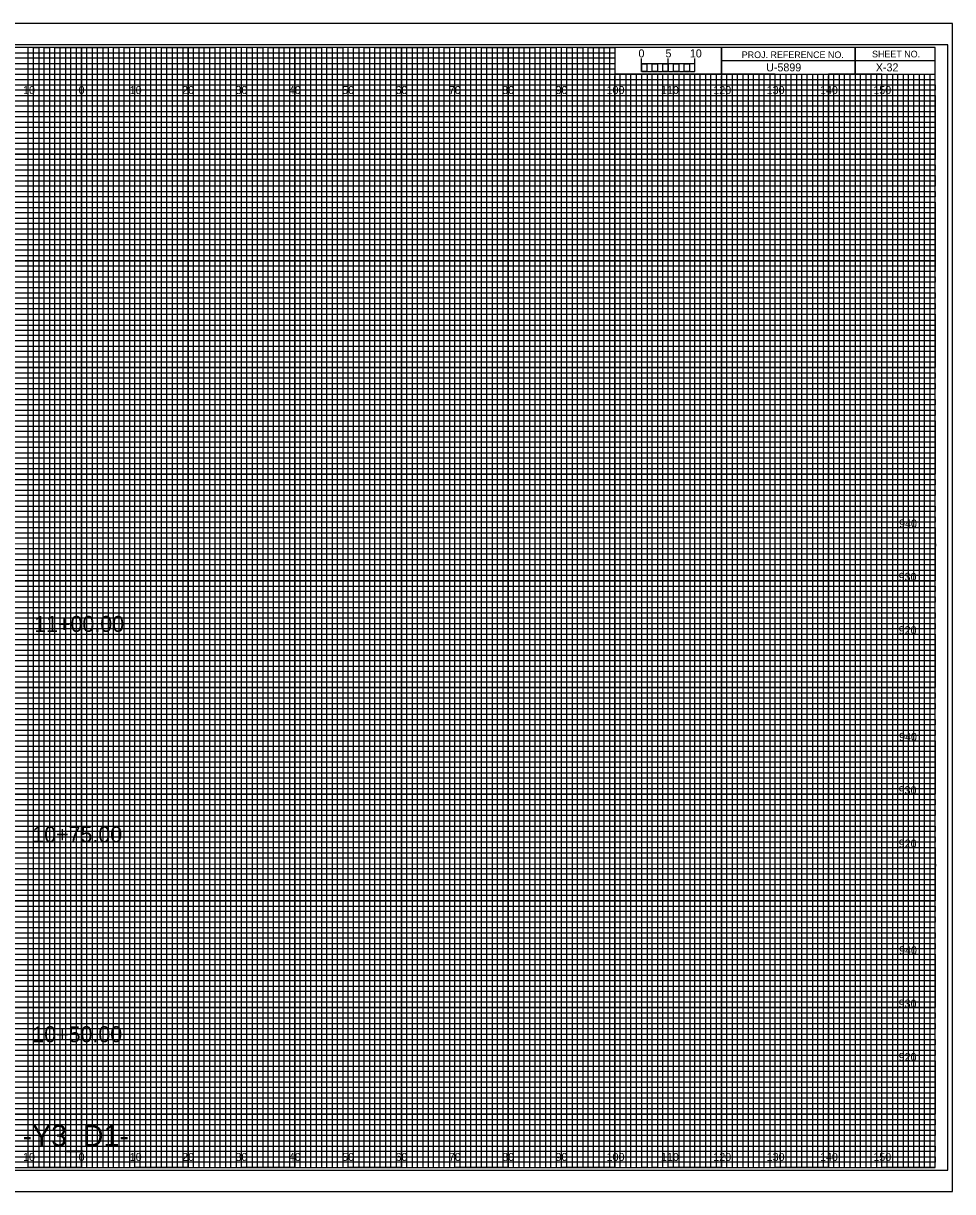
# Model space of a CAD drawing. Extents: x -13 to 323, y -4 to 214.
# Drawn here: x 149.1 to 323.3, y -4.5 to 214.5 of the extents above; entities that cross this region are included whole.
import ezdxf

# ---------------------------------------------------------------- set-up
doc = ezdxf.new("R2010")
doc.units = 0
for name, color, linetype in [('Prop XS Alignment Label', 7, 'Continuous'), ('Prop XS Bar Scale Labels', 7, 'Continuous'), ('Prop XS Elevation Labels', 7, 'Continuous'), ('Prop XS Offset Labels', 7, 'Continuous'), ('Prop XS Project Number', 7, 'Continuous'), ('Prop XS Sheet Number', 7, 'Continuous'), ('Prop XS Station Labels', 7, 'Continuous'), ('Sheet Cross Section CELL', 7, 'Continuous'), ('Sheet Cross Section Grid Major CELL', 7, 'Continuous'), ('Sheet Cross Section Grid Middle CELL', 7, 'Continuous'), ('Sheet Cross Section Grid Minor 1 CELL', 7, 'Continuous'), ('Sheet Cross Section Grid Minor 2 CELL', 7, 'Continuous'), ('Sheet Cross Section Scale CELL', 7, 'Continuous'), ('Sheet Cutting Line CELL', 7, 'Continuous'), ('Sheet DOT Grid CELL', 7, 'Continuous'), ('Sheet Plot Border Inside CELL', 7, 'Continuous'), ('Sheet Plot Border Outside CELL', 7, 'Continuous')]:
    doc.layers.add(name, color=color, linetype=linetype)

msp = doc.modelspace()

# ---------------------------------------------------------------- linework, layer by layer
at = {"layer": 'Sheet Cross Section CELL'}
for p, q in [((305, 210), (305, 205)), ((305, 205), (305, 210)), ((280, 207.5), (280, 205)), ((320, 207.49), (280, 207.49)), ((280, 205), (320, 205))]:
    msp.add_line(p, q, dxfattribs=at)
for points in [[(320, 210), (0, 210), (0, 0), (320, 0)], [(280, 210), (260, 210), (260, 205.03), (280, 205.03)], [(320, 210), (280, 210), (280, 205), (320, 205)]]:
    msp.add_lwpolyline(points, close=True, dxfattribs=at)
at = {"layer": 'Sheet Cross Section Grid Major CELL'}
for p, q in [((150, 210), (140, 210)), ((150, 0), (150, 210)), ((170, 210), (160, 210)), ((160, 210), (160, 0)), ((170, 0), (170, 210)), ((190, 210), (180, 210)), ((180, 210), (180, 0)), ((190, 0), (190, 210)), ((210, 210), (200, 210)), ((200, 210), (200, 0)), ((210, 0), (210, 210)), ((230, 210), (220, 210)), ((220, 210), (220, 0)), ((230, 0), (230, 210)), ((250, 210), (240, 210)), ((240, 210), (240, 0)), ((250, 0), (250, 210)), ((260, 210), (260, 0)), ((270, 0), (270, 205)), ((290, 205), (280, 205)), ((280, 205), (280, 0)), ((290, 0), (290, 205)), ((310, 205), (300, 205)), ((300, 205), (300, 0)), ((310, 0), (310, 205)), ((160, 0), (150, 0)), ((180, 0), (170, 0)), ((200, 0), (190, 0)), ((220, 0), (210, 0)), ((240, 0), (230, 0)), ((260, 0), (250, 0)), ((280, 0), (270, 0)), ((300, 0), (290, 0)), ((320, 0), (310, 0)), ((320, 0), (320, 0))]:
    msp.add_line(p, q, dxfattribs=at)
for points in [[(0, 200), (320, 200), (320, 190), (0, 190)], [(0, 180), (320, 180), (320, 170), (0, 170)], [(0, 160), (320, 160), (320, 150), (0, 150)], [(0, 140), (320, 140), (320, 130), (0, 130)], [(0, 120), (320, 120), (320, 110), (0, 110)], [(0, 100), (320, 100), (320, 90), (0, 90)], [(0, 80), (320, 80), (320, 70), (0, 70)], [(0, 60), (320, 60), (320, 50), (0, 50)], [(0, 40), (320, 40), (320, 30), (0, 30)], [(0, 20), (320, 20), (320, 10), (0, 10)]]:
    msp.add_lwpolyline(points, dxfattribs=at)
at = {"layer": 'Sheet Cross Section Grid Middle CELL'}
for points in [[(145, 0), (155, 0), (155, 210), (165, 210), (165, 0), (175, 0), (175, 210), (185, 210), (185, 0), (195, 0), (195, 210), (205, 210), (205, 0), (215, 0), (215, 210), (225, 210), (225, 0), (235, 0), (235, 210), (245, 210), (245, 0), (255, 0), (255, 210), (259.93, 210), (260, 210), (260, 205), (264.99, 205), (264.99, 0), (275, 0), (275, 205), (285, 205), (285, 0), (295, 0), (295, 205), (305, 205), (305, 0), (315, 0), (315, 205)], [(0, 205), (275, 205)], [(0, 185), (320, 185), (320, 195), (0, 195)], [(0, 165), (320, 165), (320, 175), (0, 175)], [(0, 145), (320, 145), (320, 155), (0, 155)], [(0, 125), (320, 125), (320, 135), (0, 135)], [(0, 105), (320, 105), (320, 115), (0, 115)], [(0, 85), (320, 85), (320, 95), (0, 95)], [(0, 65), (320, 65), (320, 75), (0, 75)], [(0, 45), (320, 45), (320, 55), (0, 55)], [(0, 25), (320, 25), (320, 35), (0, 35)], [(0, 5), (320, 5), (320, 15), (0, 15)]]:
    msp.add_lwpolyline(points, dxfattribs=at)
at = {"layer": 'Sheet Cross Section Grid Minor 1 CELL'}
for p, q in [((0, 209), (260, 209)), ((260, 209), (260, 207.98)), ((260, 207.98), (0, 207.98)), ((0, 207), (260, 207)), ((260, 205.89), (0, 205.89)), ((260, 207), (260, 205.89)), ((0, 204), (320, 204))]:
    msp.add_line(p, q, dxfattribs=at)
for points in [[(0, 203), (270, 203), (320, 203), (320, 202), (0, 202)], [(0, 201), (320, 201), (320, 199), (0, 199)], [(0, 198), (320, 198), (320, 197), (0, 196.98)], [(0, 196), (320, 196), (320, 194), (0, 194)], [(0, 193), (320, 193), (320, 192), (0, 192)], [(0, 191), (320, 191), (320, 189), (0, 189)], [(0, 188), (320, 188), (320, 187), (0, 187)], [(0, 186), (320, 186), (320, 184), (0, 184)], [(0, 183), (320, 183), (320, 182), (0, 182)], [(0, 181), (320, 181), (320, 179), (0, 179)], [(0, 178), (320, 178), (320, 177), (0, 177)], [(0, 176), (320, 176), (320, 173.95), (320, 173), (320, 172), (0, 172)], [(0, 174), (320, 174), (320, 173), (0, 173)], [(0, 171), (320, 171), (320, 169), (0, 169.03)], [(0, 169.03), (320, 169), (320, 168), (0, 168)], [(0, 167), (320, 167), (320, 166), (0, 166)], [(0, 164), (320, 164), (320, 163), (0, 163)], [(0, 162), (320, 162), (320, 161), (0, 161)], [(-0.07, 158.89), (320, 158.89), (320, 157.88), (-0.07, 157.88)], [(0, 157), (320, 157), (320, 156), (0, 156)], [(0, 154), (320, 154), (320, 153), (0, 153)], [(0, 152), (320, 152), (320, 151), (0, 151)], [(0, 149), (320, 149), (320, 148), (0, 148)], [(0, 147), (320, 147), (320, 146), (0, 146)], [(0, 144), (320, 144), (320, 143), (0, 143)], [(0, 142), (320, 142), (320, 141), (0, 141)], [(0, 139), (320, 139), (319.99, 137.98), (0, 138)], [(0, 137), (320, 137), (320, 136), (0, 136)], [(0, 134), (320, 134), (320, 133), (0, 133)], [(0, 132), (320, 132), (320, 131), (0, 131)], [(0, 129), (320, 129), (320, 128), (0, 128)], [(0, 127), (320, 127), (320, 126), (0, 126)], [(0, 124), (320, 124), (320, 123), (0, 123)], [(0, 122), (320, 122), (320, 121), (0, 121)], [(0, 119), (320, 119), (320, 118), (0, 118)], [(0, 116.99), (320.07, 116.91), (320, 116), (0, 116)], [(0, 114), (320, 114), (320, 113), (0, 113)], [(0, 112), (320, 112), (320, 111), (0, 111)], [(0, 109), (320, 109), (320, 108), (0, 108)], [(0, 107), (320, 107), (320, 106), (0, 106)], [(0, 104), (320, 104), (320, 103), (0, 103)], [(0, 102), (320, 102), (320, 101), (0, 101)], [(0, 99), (320, 99), (320, 98), (0, 98)], [(0, 97), (320, 97), (320, 96), (0, 96)], [(0, 94), (320, 94), (320, 93), (0, 93)], [(0, 92), (320, 92), (320, 91), (0, 91)], [(0, 89), (320, 89), (320, 88), (0, 88)], [(0, 87), (320, 87), (320, 86), (0, 86)], [(0, 84), (320, 84), (320, 83), (0, 83)], [(0, 82), (320, 82), (320, 81), (0, 81)], [(0, 79), (320, 79), (319.99, 77.98), (0, 78)], [(0, 77), (320, 77), (320, 76), (0, 76)], [(0, 74), (320, 74), (320, 73), (0, 73)], [(0, 72), (320, 72), (320, 71), (0, 71)], [(0, 69), (320, 69), (320, 68), (0, 68)], [(0, 67), (320, 67), (320, 66), (0, 66)], [(0, 64), (320, 64), (320, 63), (0, 63)], [(0, 62), (320, 62), (320, 61), (0, 61)], [(0, 59), (320, 59), (320, 58), (0, 58)], [(0, 56.99), (320.07, 56.91), (320, 56), (0, 56)], [(0, 54), (320, 54), (320, 53), (0, 53)], [(0, 52), (320, 52), (320, 51), (0, 51)], [(0, 49), (320, 49), (320, 48), (0, 48)], [(0, 47), (320, 47), (320, 46), (0, 46)], [(0, 44), (320, 44), (320, 43), (0, 43)], [(0, 42), (320, 42), (320, 41), (0, 41)], [(0, 39), (320, 39), (320, 38), (0, 38)], [(0, 37), (320, 37), (320, 36), (0, 36)], [(0, 34), (320, 34), (320, 33), (0, 33)], [(0, 32), (320, 32), (320, 31), (0, 31)], [(0, 29), (320, 29), (320, 28), (0, 28)], [(0, 27), (320, 27), (320, 26), (0, 26)], [(0, 24), (320, 24), (320, 23), (0, 23)], [(0, 22), (320, 22), (320, 21), (0, 21)], [(0, 19), (320, 19), (320, 18), (0, 18)], [(0, 17), (320, 17), (320, 16), (0, 16)], [(0, 14), (320, 14), (320, 13), (0, 13)], [(0, 12), (320, 12), (320, 11), (0, 11)], [(0, 9), (320, 9), (320, 8), (0, 8)], [(0, 7), (320, 7), (320, 6), (0, 6)], [(0, 4), (320, 4), (320, 3), (0, 3)], [(0, 2), (320, 2), (320, 1), (0, 1)]]:
    msp.add_lwpolyline(points, dxfattribs=at)
at = {"layer": 'Sheet Cross Section Grid Minor 2 CELL'}
for p, q in [((267, 205), (266.01, 205)), ((266.01, 205), (266.01, 0)), ((267, 0), (267, 205)), ((269, 205), (268, 205)), ((268, 205), (268, 0)), ((269, 0), (269, 205)), ((266.01, 0), (265, 0)), ((268, 0), (267, 0))]:
    msp.add_line(p, q, dxfattribs=at)
for points in [[(150, 0), (151, 0), (151, 210), (152, 210), (152, 0)], [(152, 0), (153, 0), (153, 210), (154, 210), (154, 0)], [(155, 0), (156, 0), (156, 210), (157, 210), (157, 0)], [(157, 0), (158, 0), (158, 210), (159, 210), (159, 0)], [(160, 0), (161, 0), (161, 210), (162, 210), (162, 0)], [(162, 0), (163, 0), (163, 210), (164, 210), (164, 0)], [(165, 0), (166, 0), (166, 210), (167, 210), (167, 0)], [(167, 0), (168, 0), (168, 210), (169, 210), (169, 0)], [(170, 0), (171, 0), (171, 210), (172, 210), (172, 0)], [(172, 0), (173, 0), (173, 210), (174, 210), (174, 0)], [(175, 0), (176, 0), (176, 210), (177, 210), (177, 0)], [(177, 0), (178, 0), (178, 210), (179, 210), (179, 0)], [(180, 0), (181, 0), (181, 210), (182, 210), (182, 0)], [(182, 0), (183, 0), (183, 210), (184, 210), (184, 0)], [(185, 0), (186, 0), (186, 210), (187, 210), (187, 0)], [(187, 0), (188, 0), (188, 210), (189, 210), (189, 0)], [(190, 0), (191, 0), (191, 210), (192, 210), (192, 0)], [(192, 0), (193, 0), (193, 210), (194, 210), (194, 0)], [(195, 0), (196, 0), (196, 210), (197, 210), (197, 0)], [(197, 0), (198, 0), (198, 210), (199, 210), (199, 0)], [(200, 0), (201, 0), (201, 210), (202, 210), (202, 0)], [(202, 0), (203, 0), (203, 210), (204, 210), (204, 0)], [(205, 0), (206, 0), (206, 210), (207, 210), (207, 0)], [(207, 0), (208, 0), (208, 210), (209, 210), (209, 0)], [(210, 0), (211, 0), (211, 210), (212, 210), (212, 0)], [(212, 0), (213, 0), (213, 210), (214, 210), (214, 0)], [(215, 0), (216, 0), (216, 210), (217, 210), (217, 0)], [(217, 0), (218, 0), (218, 210), (219, 210), (219, 0)], [(220, 0), (221, 0), (221, 210), (222, 210), (222, 0)], [(222, 0), (223, 0), (223, 210), (224, 210), (224, 0)], [(225, 0), (226, 0), (226, 210), (227, 210), (227, 0)], [(227, 0), (228, 0), (228, 210), (229, 210), (229, 0)], [(230, 0), (231, 0), (231, 210), (232, 210), (232, 0)], [(232, 0), (233, 0), (233, 210), (234, 210), (234, 0)], [(235, 0), (236, 0), (236, 210), (237, 210), (237, 0)], [(237, 0), (238, 0), (238, 210), (239, 210), (239, 0)], [(240, 0), (241, 0), (241, 210), (242, 210), (242, 0)], [(242, 0), (243, 0), (243, 210), (244, 210), (244, 0)], [(245, 0), (246, 0), (246, 210), (247, 210), (247, 0)], [(247, 0), (248, 0), (248, 210), (249, 210), (249, 0)], [(250, 0), (251, 0), (251, 210), (252, 210), (252, 0)], [(252, 0), (253, 0), (253, 210), (254, 210), (254, 0)], [(255, 0), (256, 0), (256, 210), (257, 210), (257, 0)], [(257, 0), (258, 0), (258, 210), (259, 210), (259, 0)], [(260, 0), (261, 0), (261, 205), (262.02, 205), (262.02, 0)], [(262, 0), (263, 0), (263, 205), (263.99, 205), (263.99, 0)], [(270, 0), (270.98, 0), (270.98, 205), (272, 205), (272, 0)], [(272, 0), (273, 0), (273, 205), (274.05, 205), (274.05, 0)], [(275, 0), (276, 0), (276, 205), (277, 205), (277, 0)], [(277, 0), (278, 0), (278, 205), (279, 205), (279, 0)], [(280, 0), (281, 0), (281, 205), (282, 205), (282, 0)], [(282, 0), (283, 0), (283, 205), (284, 205), (284, 0)], [(285, 0), (286, 0), (286, 205), (287, 205), (287, 0)], [(287, 0), (288, 0), (288, 205), (289, 205), (289, 0)], [(290, 0), (291, 0), (291, 205), (292, 205), (292, 0)], [(292, 0), (293, 0), (293, 205), (294, 205), (294, 0)], [(295, 0), (296, 0), (296, 205), (297, 205), (297, 0)], [(297, 0), (298, 0), (298, 205), (299, 205), (299, 0)], [(300, 0), (301, 0), (301, 205), (302, 205), (302, 0)], [(302, 0), (303, 0), (303, 205), (304, 205), (304, 0)], [(305, 0), (306, 0), (306, 205), (307, 205), (307, 0)], [(307, 0), (308, 0), (308, 205), (309, 205), (309, 0)], [(310, 0), (311, 0), (311, 205), (312, 205), (312, 0)], [(312, 0), (313, 0), (313, 205), (314, 205), (314, 0)], [(315, 0), (316, 0), (316, 205), (317, 205), (317, 0)], [(317, 0), (318, 0), (318, 205), (319, 205), (319, 0)]]:
    msp.add_lwpolyline(points, dxfattribs=at)
at = {"layer": 'Sheet Cross Section Scale CELL'}
for p, q in [((265, 205.49), (265, 207.9)), ((265, 206.9), (265, 207.9)), ((270, 205.49), (270, 207.9)), ((275, 205.49), (275, 207.9)), ((275, 206.9), (275, 207.9))]:
    msp.add_line(p, q, dxfattribs=at)
for points in [[(275, 206.9), (265, 206.9), (265, 205.49), (275, 205.49)], [(265, 206.9), (266, 206.9), (266, 205.49), (265, 205.49)], [(267, 206.9), (268, 206.9), (268, 205.49), (267, 205.49)], [(269, 206.9), (270, 206.9), (270, 205.49), (269, 205.49)], [(271, 206.9), (272, 206.9), (272, 205.49), (271, 205.49)], [(273, 206.9), (274, 206.9), (274, 205.49), (273, 205.49)]]:
    msp.add_lwpolyline(points, close=True, dxfattribs=at)
at = {"layer": 'Sheet Cutting Line CELL'}
for p, q in [((323.3, 214.5), (-13.4, 214.5)), ((-13.4, -4.5), (323.3, -4.5))]:
    msp.add_line(p, q, dxfattribs=at)
at = {"layer": 'Sheet DOT Grid CELL'}
for p, q in [((150, 0), (150, 210)), ((160, 0), (160, 210)), ((170, 0), (170, 210)), ((180, 0), (180, 210)), ((190, 0), (190, 210)), ((200, 0), (200, 210)), ((210, 0), (210, 210)), ((220, 0), (220, 210)), ((230, 0), (230, 210)), ((240, 0), (240, 210)), ((250, 0), (250, 210)), ((260, 0), (260, 204.69)), ((270, 0), (270, 204.69)), ((280, 0), (280, 204.69)), ((290, 0), (290, 204.69)), ((300, 0), (300, 204.69)), ((310, 0), (310, 204.69)), ((0, 200), (320, 200)), ((0, 190), (320, 190)), ((0, 180), (320, 180)), ((0, 170), (320, 170)), ((0, 160), (320, 160)), ((0, 150), (320, 150)), ((0, 140), (320, 140)), ((0, 130), (320, 130)), ((0, 120), (320, 120)), ((0, 110), (320, 110)), ((0, 100), (320, 100)), ((0, 90), (320, 90)), ((0, 80), (320, 80)), ((0, 70), (320, 70)), ((0, 60), (320, 60)), ((0, 50), (320, 50)), ((0, 40), (320, 40)), ((0, 30), (320, 30)), ((0, 20), (320, 20)), ((0, 10), (320, 10))]:
    msp.add_line(p, q, dxfattribs=at)
at = {"layer": 'Sheet Plot Border Inside CELL'}
msp.add_lwpolyline([(-10.8, -0.5), (322.4, -0.5), (322.4, 210.5), (-10.8, 210.5)], close=True, dxfattribs=at)
at = {"layer": 'Sheet Plot Border Outside CELL'}
msp.add_lwpolyline([(-13.4, -4.5), (323.3, -4.5), (323.3, 214.5), (-13.4, 214.5)], close=True, dxfattribs=at)

# ---------------------------------------------------------------- texts
at = {"layer": 'Prop XS Alignment Label'}
msp.add_text('-Y3_D1-', height=4, dxfattribs=at).set_placement((148.95, 4))
at = {"layer": 'Prop XS Bar Scale Labels'}
for s, p in [('5', (269.47, 208.12)), ('10', (274.04, 208.12))]:
    msp.add_text(s, height=1.5, dxfattribs=at).set_placement(p)
at = {"layer": 'Prop XS Elevation Labels'}
for s, p in [('940', (313.26, 120)), ('930', (313.18, 110)), ('920', (313.19, 100)), ('940', (313.26, 80)), ('930', (313.18, 70)), ('920', (313.19, 60)), ('940', (313.26, 40)), ('930', (313.18, 30)), ('920', (313.19, 20))]:
    msp.add_text(s, height=1.5, dxfattribs=at).set_placement(p)
at = {"layer": 'Prop XS Offset Labels'}
for s, p in [('10', (149.04, 201.25)), ('0', (159.45, 201.25)), ('0', (159.45, 201.25)), ('10', (169.04, 201.25)), ('20', (178.86, 201.25)), ('30', (188.86, 201.25)), ('40', (198.86, 201.25)), ('50', (208.86, 201.25)), ('60', (218.86, 201.25)), ('70', (228.86, 201.25)), ('80', (238.86, 201.25)), ('90', (248.86, 201.25)), ('100', (258.44, 201.25)), ('110', (268.62, 201.25)), ('120', (278.44, 201.25)), ('130', (288.44, 201.25)), ('140', (298.44, 201.25)), ('150', (308.44, 201.25)), ('10', (149.04, 1.25)), ('0', (159.45, 1.25)), ('0', (159.45, 1.25)), ('10', (169.04, 1.25)), ('20', (178.86, 1.25)), ('30', (188.86, 1.25)), ('40', (198.86, 1.25)), ('50', (208.86, 1.25)), ('60', (218.86, 1.25)), ('70', (228.86, 1.25)), ('80', (238.86, 1.25)), ('90', (248.86, 1.25)), ('100', (258.44, 1.25)), ('110', (268.62, 1.25)), ('120', (278.44, 1.25)), ('130', (288.44, 1.25)), ('140', (298.44, 1.25)), ('150', (308.44, 1.25))]:
    msp.add_text(s, height=1.5, dxfattribs=at).set_placement(p)
at = {"layer": 'Prop XS Project Number'}
msp.add_text('U-5899', height=1.5, dxfattribs=at).set_placement((288.34, 205.5))
at = {"layer": 'Prop XS Sheet Number'}
msp.add_text('X-32', height=1.5, dxfattribs=at).set_placement((308.9, 205.5))
at = {"layer": 'Prop XS Station Labels'}
for s, p in [('11+00.00', (151.13, 100.42)), ('10+75.00', (150.77, 60.97)), ('10+50.00', (150.77, 23.51))]:
    msp.add_text(s, height=3, dxfattribs=at).set_placement(p)
at = {"layer": 'Sheet Cross Section CELL'}
for s, p in [('PROJ. REFERENCE NO.', (283.77, 207.99)), ('SHEET NO.', (308.19, 208.12))]:
    msp.add_text(s, height=1.25, dxfattribs=at).set_placement(p)
at = {"layer": 'Sheet Cross Section Scale CELL'}
msp.add_text('0', height=1.5, dxfattribs=at).set_placement((264.41, 208.12))

doc.saveas('drawing.dxf')
